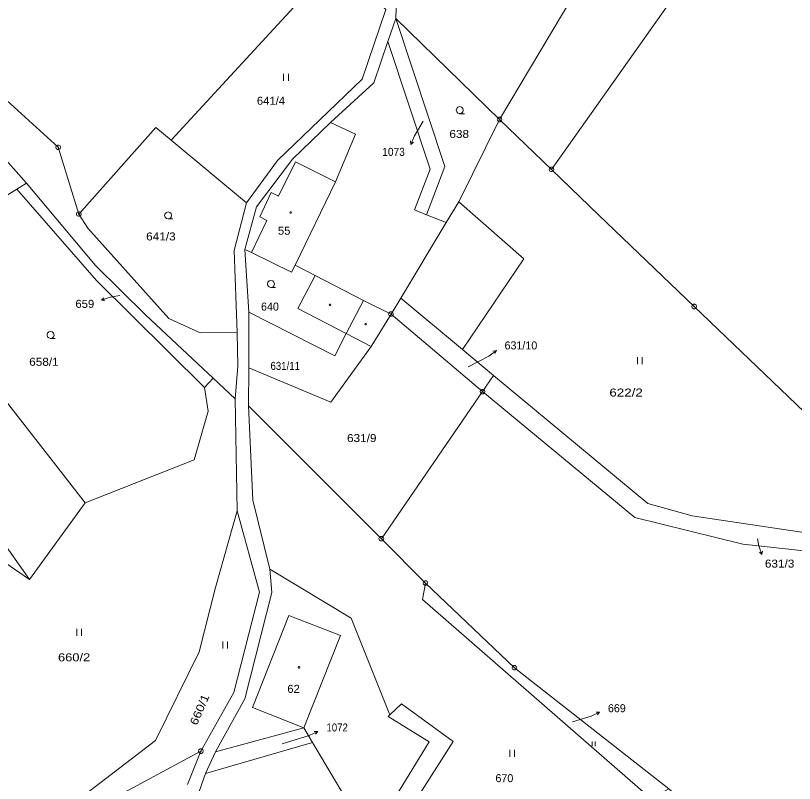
# Model space of a CAD drawing. Extents: x -687390 to -684106, y -954833 to -951648.
# Drawn here: x -687041.5 to -686876.1, y -953282.2 to -953119.1 of the extents above; entities that cross this region are included whole.
import ezdxf
from ezdxf.enums import TextEntityAlignment as Align

# ---------------------------------------------------------------- set-up
doc = ezdxf.new("R2010")
doc.units = 0
doc.header["$LTSCALE"] = 0.68
for name, color, linetype, lineweight in [('1', 7, 'Continuous', 13), ('3', 7, 'Continuous', 13), ('4', 7, 'Continuous', 13), ('5', 7, 'Continuous', 13), ('7', 7, 'Continuous', 13), ('8', 7, 'Continuous', 13)]:
    doc.layers.add(name, color=color, linetype=linetype, lineweight=lineweight)
doc.layers.add('2', color=7, linetype='Continuous')

msp = doc.modelspace()

# ---------------------------------------------------------------- linework, layer by layer
at = {"layer": '1'}
for p, q in [((-686901.43, -953078.42), (-686938.75, -953141.17)), ((-686960.79, -953119.7), (-686960.07, -953096.32)), ((-686960.79, -953119.7), (-686938.75, -953141.17)), ((-686960.79, -953119.7), (-686950.35, -953151.15)), ((-686953.52, -953151.72), (-686962.48, -953124.63)), ((-686967.94, -953132.58), (-686985.9, -953149.88)), ((-686974.66, -953141.78), (-686965.48, -953133.35)), ((-687057.34, -953134.44), (-687039.19, -953154.71)), ((-686927.73, -953151.78), (-686938.75, -953141.17)), ((-686992.5, -953158.87), (-686985.9, -953149.88)), ((-686953.52, -953151.72), (-686956.86, -953160.36)), ((-686927.73, -953151.78), (-686917.71, -953161.51)), ((-687041.28, -953156), (-687024.34, -953175.39)), ((-686947.42, -953158.67), (-686950.07, -953163.06)), ((-687028.11, -953161.25), (-687026.23, -953164.27)), ((-686950.07, -953163.06), (-686954.29, -953161.39)), ((-686897.44, -953180.91), (-686917.71, -953161.51)), ((-687008.96, -953183.46), (-687026.23, -953164.27)), ((-686992.02, -953182.07), (-686992.86, -953168.77)), ((-686991.46, -953169.44), (-686992.86, -953168.77)), ((-686991.46, -953169.44), (-686982.91, -953173.58)), ((-687065.6, -953172.81), (-687026.75, -953222.62)), ((-686982.91, -953173.58), (-686982.19, -953172.11)), ((-686982.19, -953172.11), (-686977.94, -953174.32)), ((-687001.42, -953198.07), (-687024.34, -953175.39)), ((-686961.81, -953182.51), (-686959.75, -953179.12)), ((-686897.44, -953180.91), (-686867.52, -953209.56)), ((-686942.38, -953198.97), (-686961.81, -953182.51)), ((-686994.51, -953186.39), (-686994.35, -953193.58)), ((-686974.59, -953201.21), (-686966, -953189.41)), ((-686994.92, -953200.51), (-686994.35, -953193.58)), ((-686974.59, -953201.21), (-686992.04, -953193.91)), ((-686940.04, -953195.56), (-686942.38, -953198.97)), ((-686963.86, -953230.22), (-686942.38, -953198.97)), ((-686963.86, -953230.22), (-686992.06, -953201.99)), ((-686970.29, -953247.11), (-686962.09, -953267.66)), ((-686959.61, -953265.29), (-686948.59, -953273.28)), ((-686962.44, -953267.99), (-686953.7, -953273.35)), ((-686999.06, -953275.53), (-686980.31, -953270.4)), ((-687001.24, -953280.12), (-686978.45, -953273.53)), ((-686963.5, -953289.34), (-686953.7, -953273.35)), ((-686948.59, -953273.28), (-686962.93, -953295.64)), ((-687002.18, -953275.37), (-687005, -953282.45))]:
    msp.add_line(p, q, dxfattribs=at)
for points in [[(-686927.73, -953151.78), (-686885.49, -953092.02), (-686882.52, -953087.82), (-686878.63, -953082.32)], [(-686973.25, -953107.24), (-687008.47, -953145.56), (-686992.5, -953158.87)], [(-686973.25, -953107.24), (-686962.91, -953117.79), (-686967.94, -953132.58)], [(-687084.65, -953110.47), (-687068.19, -953124.81), (-687062.93, -953119.45), (-687032.49, -953147.08), (-687028.11, -953161.25)], [(-686965.48, -953133.35), (-686962.48, -953124.63), (-686960.79, -953119.7)], [(-686938.75, -953141.17), (-686947.42, -953158.67), (-686933.64, -953170.77), (-686946.66, -953190.05), (-686959.75, -953179.12)], [(-687028.11, -953161.25), (-687011.77, -953142.84), (-687008.47, -953145.56)], [(-686992.86, -953168.77), (-686990.39, -953159.71), (-686982.72, -953149.61), (-686974.66, -953141.78)], [(-686950.35, -953151.15), (-686954.29, -953161.39), (-686956.86, -953160.36)], [(-687058.51, -953166.68), (-687041.28, -953156), (-687039.19, -953154.71)], [(-687039.19, -953154.71), (-687024.54, -953172.18), (-687013.98, -953182.69)], [(-687093.49, -953158.17), (-687085.58, -953172.28), (-687038.6, -953238.91), (-687052.35, -953229.48), (-687052.31, -953285.08)], [(-686992.5, -953158.87), (-686995.12, -953168.97), (-686994.51, -953186.39)], [(-686977.94, -953174.32), (-686981.58, -953181.33), (-686971.32, -953186.65)], [(-686994.92, -953200.51), (-686999.55, -953196.12), (-687013.98, -953182.69)], [(-686992.06, -953201.99), (-686992.04, -953193.91), (-686992.02, -953182.07)], [(-686971.32, -953186.65), (-686973.76, -953191.35), (-686992.02, -953182.07)], [(-686971.32, -953186.65), (-686966, -953189.41), (-686961.81, -953182.51)], [(-687008.96, -953183.46), (-687002.34, -953186.49), (-686994.51, -953186.39)], [(-686946.66, -953190.05), (-686940.04, -953195.56), (-686907.28, -953222.77)], [(-687038.6, -953238.91), (-687026.75, -953222.62), (-687003.59, -953213.47), (-687000.66, -953203.14), (-687001.42, -953198.07), (-686999.55, -953196.12)], [(-686845.52, -953235.93), (-686887.1, -953231.37), (-686910.01, -953225.72), (-686942.38, -953198.97)], [(-686994.92, -953200.51), (-686994.51, -953224.29), (-686999.09, -953240.57), (-687002.53, -953254.23), (-687011.81, -953273.12), (-687044.58, -953298.25), (-687002.18, -953275.37), (-686995.21, -953262.9), (-686989.71, -953241.58), (-686994.51, -953224.29)], [(-686992.06, -953201.99), (-686991.14, -953222.02), (-686987.54, -953236.71), (-686970.29, -953247.11)], [(-686907.28, -953222.77), (-686897.88, -953225.38), (-686845.22, -953233.23), (-686832.78, -953245.07), (-686815.59, -953264.66)], [(-686886.6, -953297.34), (-686902.8, -953283.36), (-686935.6, -953257.64), (-686954.5, -953239.63), (-686963.86, -953230.22)], [(-686987.54, -953236.71), (-686987.1, -953241.65), (-686992.89, -953264.26), (-686999.06, -953275.53), (-687001.24, -953280.12)], [(-686954.5, -953239.63), (-686955.14, -953243.1), (-686906.67, -953285.44), (-686902.8, -953283.36)], [(-686962.44, -953267.99), (-686962.09, -953267.66), (-686959.61, -953265.29)], [(-686980.31, -953270.4), (-686978.45, -953273.53), (-686972.24, -953283.98)], [(-687001.24, -953280.12), (-687002.52, -953283.9), (-687003.27, -953290.65), (-686999.73, -953297.51), (-686983.56, -953302.91)]]:
    msp.add_lwpolyline(points, dxfattribs=at)
at = {"layer": '3'}
for p, q in [((-686984.61, -953131.44), (-686984.61, -953132.94)), ((-686983.61, -953132.94), (-686983.61, -953131.44)), ((-686909.46, -953191.65), (-686909.46, -953193.15)), ((-686908.46, -953193.15), (-686908.46, -953191.65)), ((-687028.53, -953249.34), (-687028.53, -953250.84)), ((-687027.53, -953250.84), (-687027.53, -953249.34)), ((-686997.51, -953252.04), (-686997.51, -953253.54)), ((-686996.51, -953253.54), (-686996.51, -953252.04)), ((-686919.105, -953273.285), (-686919.105, -953274.29)), ((-686918.435, -953274.29), (-686918.435, -953273.285)), ((-686936.61, -953275.06), (-686936.61, -953276.56)), ((-686935.61, -953276.56), (-686935.61, -953275.06))]:
    msp.add_line(p, q, dxfattribs=at)
for points in [[(-686947.22, -953139.91), (-686947.6, -953139.81), (-686947.87, -953139.54), (-686947.97, -953139.17), (-686947.87, -953138.8), (-686947.6, -953138.53), (-686947.23, -953138.43), (-686946.86, -953138.53), (-686946.59, -953138.8), (-686946.49, -953139.18), (-686946.59, -953139.56), (-686946.86, -953139.83), (-686947.24, -953139.93), (-686946.24, -953139.93)], [(-687009.13, -953162.27), (-687009.51, -953162.17), (-687009.78, -953161.9), (-687009.88, -953161.53), (-687009.78, -953161.16), (-687009.51, -953160.89), (-687009.14, -953160.79), (-687008.77, -953160.89), (-687008.5, -953161.16), (-687008.4, -953161.54), (-687008.5, -953161.92), (-687008.77, -953162.19), (-687009.15, -953162.29), (-687008.15, -953162.29)], [(-686987.3, -953176.83), (-686987.68, -953176.73), (-686987.95, -953176.46), (-686988.05, -953176.09), (-686987.95, -953175.72), (-686987.68, -953175.45), (-686987.31, -953175.35), (-686986.94, -953175.45), (-686986.67, -953175.72), (-686986.57, -953176.1), (-686986.67, -953176.48), (-686986.94, -953176.75), (-686987.32, -953176.85), (-686986.32, -953176.85)], [(-687034.1, -953187.68), (-687034.48, -953187.58), (-687034.75, -953187.31), (-687034.85, -953186.94), (-687034.75, -953186.57), (-687034.48, -953186.3), (-687034.11, -953186.2), (-687033.74, -953186.3), (-687033.47, -953186.57), (-687033.37, -953186.95), (-687033.47, -953187.33), (-687033.74, -953187.6), (-687034.12, -953187.7), (-687033.12, -953187.7)]]:
    msp.add_lwpolyline(points, dxfattribs=at)
at = {"layer": '4'}
for p, q in [((-686974.66, -953141.78), (-686969.37, -953144.31)), ((-686969.37, -953144.31), (-686973.6, -953154.38)), ((-686982.19, -953172.11), (-686973.6, -953154.38)), ((-686950.07, -953163.06), (-686959.75, -953179.12)), ((-686967.69, -953179.64), (-686977.94, -953174.32)), ((-686983.52, -953246.51), (-686991.26, -953266.1)), ((-686972.56, -953250.81), (-686983.52, -953246.51))]:
    msp.add_line(p, q, dxfattribs=at)
for points in [[(-686991.46, -953169.44), (-686988.16, -953162.61), (-686989.7, -953161.86), (-686987.23, -953156.7), (-686985.7, -953157.47), (-686982.09, -953150.18), (-686973.6, -953154.38)], [(-686971.32, -953186.65), (-686967.69, -953179.64), (-686961.81, -953182.51)], [(-686972.56, -953250.81), (-686980.31, -953270.4), (-686991.26, -953266.1)]]:
    msp.add_lwpolyline(points, dxfattribs=at)
at = {"layer": '5'}
for points in [[(-686983.05, -953160.78), (-686982.96, -953160.93), (-686983.05, -953161.08), (-686983.23, -953161.08), (-686983.32, -953160.93), (-686983.23, -953160.78)], [(-686974.67, -953180.41), (-686974.58, -953180.56), (-686974.67, -953180.71), (-686974.85, -953180.71), (-686974.94, -953180.56), (-686974.85, -953180.41)], [(-686967.1, -953184.51), (-686967.01, -953184.66), (-686967.1, -953184.81), (-686967.28, -953184.81), (-686967.37, -953184.66), (-686967.28, -953184.51)], [(-686981.28, -953257.39), (-686981.19, -953257.54), (-686981.28, -953257.69), (-686981.46, -953257.69), (-686981.55, -953257.54), (-686981.46, -953257.39)]]:
    msp.add_lwpolyline(points, close=True, dxfattribs=at)
at = {"layer": '7'}
for p, q in [((-686954.97, -953141.5), (-686956.85, -953144.63)), ((-686957.634, -953146.481), (-686956.85, -953144.63)), ((-687023.323, -953179.568), (-687021.42, -953178.92)), ((-687019.43, -953178.55), (-687021.42, -953178.92)), ((-686939.443, -953190.23), (-686941.07, -953191.41)), ((-686945.4, -953193.7), (-686941.07, -953191.41)), ((-686884.02, -953230.24), (-686883.72, -953231.71)), ((-686883.051, -953233.605), (-686883.72, -953231.71)), ((-686917.511, -953267.086), (-686919.34, -953267.92)), ((-686923.29, -953269.09), (-686919.34, -953267.92)), ((-686984.92, -953273.8), (-686979.18, -953272.04)), ((-686977.36, -953271.186), (-686979.18, -953272.04))]:
    msp.add_line(p, q, dxfattribs=at)
for points in [[(-686957.064, -953145.995), (-686957.634, -953146.481), (-686957.681, -953145.733)], [(-687022.58, -953179.669), (-687023.323, -953179.568), (-687022.796, -953179.035)], [(-686940.182, -953190.352), (-686939.443, -953190.23), (-686939.789, -953190.894)], [(-686882.958, -953232.862), (-686883.051, -953233.605), (-686883.59, -953233.085)], [(-686918.26, -953267.059), (-686917.511, -953267.086), (-686917.982, -953267.669)], [(-686978.109, -953271.168), (-686977.36, -953271.186), (-686977.825, -953271.774)]]:
    msp.add_lwpolyline(points, dxfattribs=at)
at = {"layer": '8'}
for p, q in [((-686938.87, -953141.17), (-686938.63, -953141.17)), ((-687032.61, -953147.08), (-687032.37, -953147.08)), ((-686927.85, -953151.78), (-686927.61, -953151.78)), ((-687028.23, -953161.25), (-687027.99, -953161.25)), ((-686897.56, -953180.91), (-686897.32, -953180.91)), ((-686961.93, -953182.51), (-686961.69, -953182.51)), ((-686942.5, -953198.97), (-686942.26, -953198.97)), ((-686963.98, -953230.22), (-686963.74, -953230.22)), ((-686954.62, -953239.63), (-686954.38, -953239.63)), ((-686935.72, -953257.64), (-686935.48, -953257.64)), ((-687002.3, -953275.37), (-687002.06, -953275.37))]:
    msp.add_line(p, q, dxfattribs=at)
for points in [[(-686938.6, -953140.69), (-686938.35, -953140.87), (-686938.25, -953141.16), (-686938.35, -953141.45), (-686938.6, -953141.63), (-686938.91, -953141.63), (-686939.16, -953141.45), (-686939.26, -953141.16), (-686939.16, -953140.87), (-686938.91, -953140.69)], [(-687032.34, -953146.6), (-687032.09, -953146.78), (-687031.99, -953147.07), (-687032.09, -953147.36), (-687032.34, -953147.54), (-687032.65, -953147.54), (-687032.9, -953147.36), (-687033, -953147.07), (-687032.9, -953146.78), (-687032.65, -953146.6)], [(-686927.58, -953151.3), (-686927.33, -953151.48), (-686927.23, -953151.77), (-686927.33, -953152.06), (-686927.58, -953152.24), (-686927.89, -953152.24), (-686928.14, -953152.06), (-686928.24, -953151.77), (-686928.14, -953151.48), (-686927.89, -953151.3)], [(-687027.96, -953160.77), (-687027.71, -953160.95), (-687027.61, -953161.24), (-687027.71, -953161.53), (-687027.96, -953161.71), (-687028.27, -953161.71), (-687028.52, -953161.53), (-687028.62, -953161.24), (-687028.52, -953160.95), (-687028.27, -953160.77)], [(-686897.29, -953180.43), (-686897.04, -953180.61), (-686896.94, -953180.9), (-686897.04, -953181.19), (-686897.29, -953181.37), (-686897.6, -953181.37), (-686897.85, -953181.19), (-686897.95, -953180.9), (-686897.85, -953180.61), (-686897.6, -953180.43)], [(-686961.66, -953182.03), (-686961.41, -953182.21), (-686961.31, -953182.5), (-686961.41, -953182.79), (-686961.66, -953182.97), (-686961.97, -953182.97), (-686962.22, -953182.79), (-686962.32, -953182.5), (-686962.22, -953182.21), (-686961.97, -953182.03)], [(-686942.23, -953198.49), (-686941.98, -953198.67), (-686941.88, -953198.96), (-686941.98, -953199.25), (-686942.23, -953199.43), (-686942.54, -953199.43), (-686942.79, -953199.25), (-686942.89, -953198.96), (-686942.79, -953198.67), (-686942.54, -953198.49)], [(-686963.71, -953229.74), (-686963.46, -953229.92), (-686963.36, -953230.21), (-686963.46, -953230.5), (-686963.71, -953230.68), (-686964.02, -953230.68), (-686964.27, -953230.5), (-686964.37, -953230.21), (-686964.27, -953229.92), (-686964.02, -953229.74)], [(-686954.35, -953239.15), (-686954.1, -953239.33), (-686954, -953239.62), (-686954.1, -953239.91), (-686954.35, -953240.09), (-686954.66, -953240.09), (-686954.91, -953239.91), (-686955.01, -953239.62), (-686954.91, -953239.33), (-686954.66, -953239.15)], [(-686935.45, -953257.16), (-686935.2, -953257.34), (-686935.1, -953257.63), (-686935.2, -953257.92), (-686935.45, -953258.1), (-686935.76, -953258.1), (-686936.01, -953257.92), (-686936.11, -953257.63), (-686936.01, -953257.34), (-686935.76, -953257.16)], [(-687002.03, -953274.89), (-687001.78, -953275.07), (-687001.68, -953275.36), (-687001.78, -953275.65), (-687002.03, -953275.83), (-687002.34, -953275.83), (-687002.59, -953275.65), (-687002.69, -953275.36), (-687002.59, -953275.07), (-687002.34, -953274.89)]]:
    msp.add_lwpolyline(points, close=True, dxfattribs=at)

# ---------------------------------------------------------------- texts
at = {"layer": '2'}
for s, height, width, p in [('641/4', 1.7, 1.05, (-686990.296, -953138.04)), ('1073', 0.1, 0.95, (-686954.924, -953141.5)), ('638', 1.7, 1.1, (-686949.416, -953145.09)), ('55', 1.7, 1.05, (-686985.835, -953165.64)), ('641/3', 1.7, 1.1, (-687013.806, -953166.86)), ('659', 0.1, 1.05, (-687019.388, -953178.55)), ('658/1', 1.7, 1.1, (-687038.646, -953193.49)), ('631/11', 1.7, 0.9, (-686987.406, -953194.36)), ('622/2', 1.7, 1.25, (-686915.446, -953200.02)), ('631/9', 1.7, 1.1, (-686971.156, -953209.69)), ('631/3', 0.1, 1.1, (-686883.978, -953230.24)), ('660/2', 1.7, 1.2, (-687032.526, -953256.27)), ('62', 1.7, 1.05, (-686983.836, -953262.97)), ('1072', 0.1, 0.9, (-686984.874, -953273.8))]:
    msp.add_text(s, height=height, dxfattribs=dict(at, width=width)).set_placement(p)
for s, height, p in [('640', 1.7, (-686989.416, -953181.76)), ('631/10', 0.1, (-686945.358, -953193.7)), ('669', 0.1, (-686923.248, -953269.09)), ('670', 1.7, (-686939.636, -953281.94))]:
    msp.add_text(s, height=height, dxfattribs=at).set_placement(p)
at = {"layer": '2', "width": 1.2}
msp.add_text('660/1', height=1.7, rotation=66.807, dxfattribs=at).set_placement((-687003.039, -953270.004))
at = {"layer": '7'}
for s, width, p in [('1073', 0.95, (-686958.876, -953148.89)), ('659', 1.05, (-687024.846, -953181.18))]:
    msp.add_text(s, height=1.7, dxfattribs=dict(at, width=width)).set_placement(p, align=Align.RIGHT)
for s, p in [('631/10', (-686937.706, -953190.01)), ('669', (-686915.746, -953267.08))]:
    msp.add_text(s, height=1.7, dxfattribs=at).set_placement(p)
for s, width, p in [('631/3', 1.1, (-686882.416, -953236.36)), ('1072', 0.9, (-686975.525, -953271.17))]:
    msp.add_text(s, height=1.7, dxfattribs=dict(at, width=width)).set_placement(p)

doc.saveas('drawing.dxf')
